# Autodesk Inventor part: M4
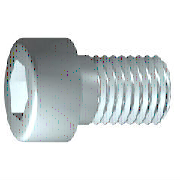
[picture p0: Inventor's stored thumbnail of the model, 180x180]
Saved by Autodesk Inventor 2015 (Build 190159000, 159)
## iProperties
IsCustomPart: 0
Created: 2014-10
Part Number: M4
Material: 강철, 연강
Description: 6각머리 태핑 나사
Document SubType Name: Modeling
Standard: KS B 1003
Designer: KYOUNG IL JANG
Standards Organization: KS
Language: ko-KR
Size Designation: M 4 x 10
Categories: <MemberInstance><Categories><Category DisplayName="조임쇠" InternalName="e4da775c-781d-43d5-af7c-5136215cf5a6" Mnemonic="FSTN"><Category DisplayName="볼트" InternalN
Density: 7.86 g/cm^3
Mass: 2.0371 g
Surface Area: 3.0572 cm^2
Volume: 0.259174 cm^3
Appearance: Black Cast
Author: SeoGD™ [www.esajin.kr]
Revision Number: 1
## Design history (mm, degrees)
sketch "스케치1"
  geometry: L1 (-1, 0)-(10, 0); L2 (10, 0)-(10, 2); L3 (10, 2)-(1.75, 2); L4 (1.75, 2)-(1.32, 2); L5 (1.32, 2)-(0, 2); L6 (0, 2)-(0, 3.5); L7 (0, 3.5)-(-4, 3.5); L8 (-4, 3.5)-(-4, 1.732); L9 (-4, 1.732)-(-2, 1.732); L10 (-2, 1.732)-(-1, 0); L11 (-6.8, 0)-(12.8, 0) reference; L12 (0, -0.7)-(0, 4.2) reference; L13 (1.75, 2)-(0, 2)
  constraints: 22 end point, 6 parallel, 2 collinear, 2 perpendicular, 1 horizontal, 1 point on line
  dimensions: "d1" = 8.25 distance from line of L3.end L2 (= GEL); "d2" = 0.42952 distance of L4.end L3.end (computed from GAL); "d3" = 4 distance between parallel lines of L8 L6 (= KOH); "d4" = 2 distance of L8.end L9.end (= INTI); "d5" = 60 deg angle of L10 L1; "d6" = 4 diameter of L3 L1 (= GD); "d7" = 4 diameter of L5 L1 (= BDM); "d8" = 3.4641 diameter of L9 L1 (= 1.1547 x SW); "d9" = 7 diameter of L7 L1 (= KOD); "d26" = 10 distance between parallel lines of L12 L2 (= NLG)
revolve "본체" sketch "스케치1" stored, may be unused: angle "d10" = 90 deg
sketch "스케치2"
  geometry: L1 (0, -4.9)-(0, 4.9) reference; L2 (-4.9, 0)-(4.9, 0) reference; L3 (1.732, 0)-(0.866, -1.5); L4 (0.866, -1.5)-(-0.866, -1.5); L5 (-0.866, -1.5)-(-1.732, 0); L6 (-1.732, 0)-(-0.866, 1.5); L7 (-0.866, 1.5)-(0.866, 1.5); L8 (0.866, 1.5)-(1.732, 0); 2 further points
  constraints: 12 end point, 1 coincident, 1 horizontal alignment, 1 point on line, 12 other
extrude "슬롯" join sketch "스케치2" stored distance "d11" = 10; taper "d12" = 0 deg
workplane "Work Plane1"
fillet "Fillet2" dims "d30" = 0.1 (= R)
body "Solid1"
fillet "모깎기1" dims "d17" = 0.4 (= RR)
feature "스레드" dims "d13" = 8.25 (= GEL), "d14" = 0
chamfer "모따기1" distance "d15" = 0.42941 (= -0.5 x SPD + 0.5 x GD); stored, may be unused: second distance "d16" = 0.42941 (= GUL), angle "d27" = 45 deg
other parameters: "GD" = 4 (= NND) [user parameter; used in 2 equation terms], "NLG" = 10 [user parameter; used in 1 equation term], "GEL" = 8.25 [user parameter; used in 2 equation terms], "KOD" = 7 [user parameter; used in 1 equation term], "KOH" = 4 [user parameter; used in 1 equation term], "INTI" = 2 [user parameter; used in 1 equation term], "GAL" = 0.42941 (= 0.61345 x PTC) [user parameter; used in 1 equation term], "GUL" = 0.42941 (= 0.61345 x PTC) [user parameter; used in 1 equation term], "BDM" = 4 (= NND) [user parameter; used in 1 equation term], "SW" = 3 [user parameter; used in 2 equation terms], "RR" = 0.4 [user parameter; used in 1 equation term], "SPD" = 3.14117 (= NND - 1.2269 x PTC) [user parameter; used in 1 equation term], "d19" = 0, "d28" = 0, "d29" = 0, "R" = 0.1 [user parameter; used in 1 equation term], "PHH" = 0.2 [user parameter], "GD1" = 3.14117 (= THREADDIA - 1.2269 x PTC) [user parameter], "THREADDIA" = 4 [user parameter; used in 1 equation term], "FAWI" = 45 deg [user parameter], "TPU" = 14.28571 (computed from PTC) [user parameter], "PTC" = 0.7 [user parameter; used in 5 equation terms], "NND" = 4 [user parameter; used in 3 equation terms], "TOA" = 30 deg [user parameter], "E0" = 3.465 (= 1.155 x SW) [user parameter]
